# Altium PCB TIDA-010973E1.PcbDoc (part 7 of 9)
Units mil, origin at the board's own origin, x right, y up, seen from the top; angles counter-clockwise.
Board outline 5166 x 3669 mil, 8 copper layers (L01 - TOP, L02 - GND, L03 - SIG, L04 - GND, L05 - PWR, L06 - SIG, L07 - GND, L08 - BOTTOM), stack 61.7 mil thick; 677 components, 493 nets, 2522 pads, 1424 vias.
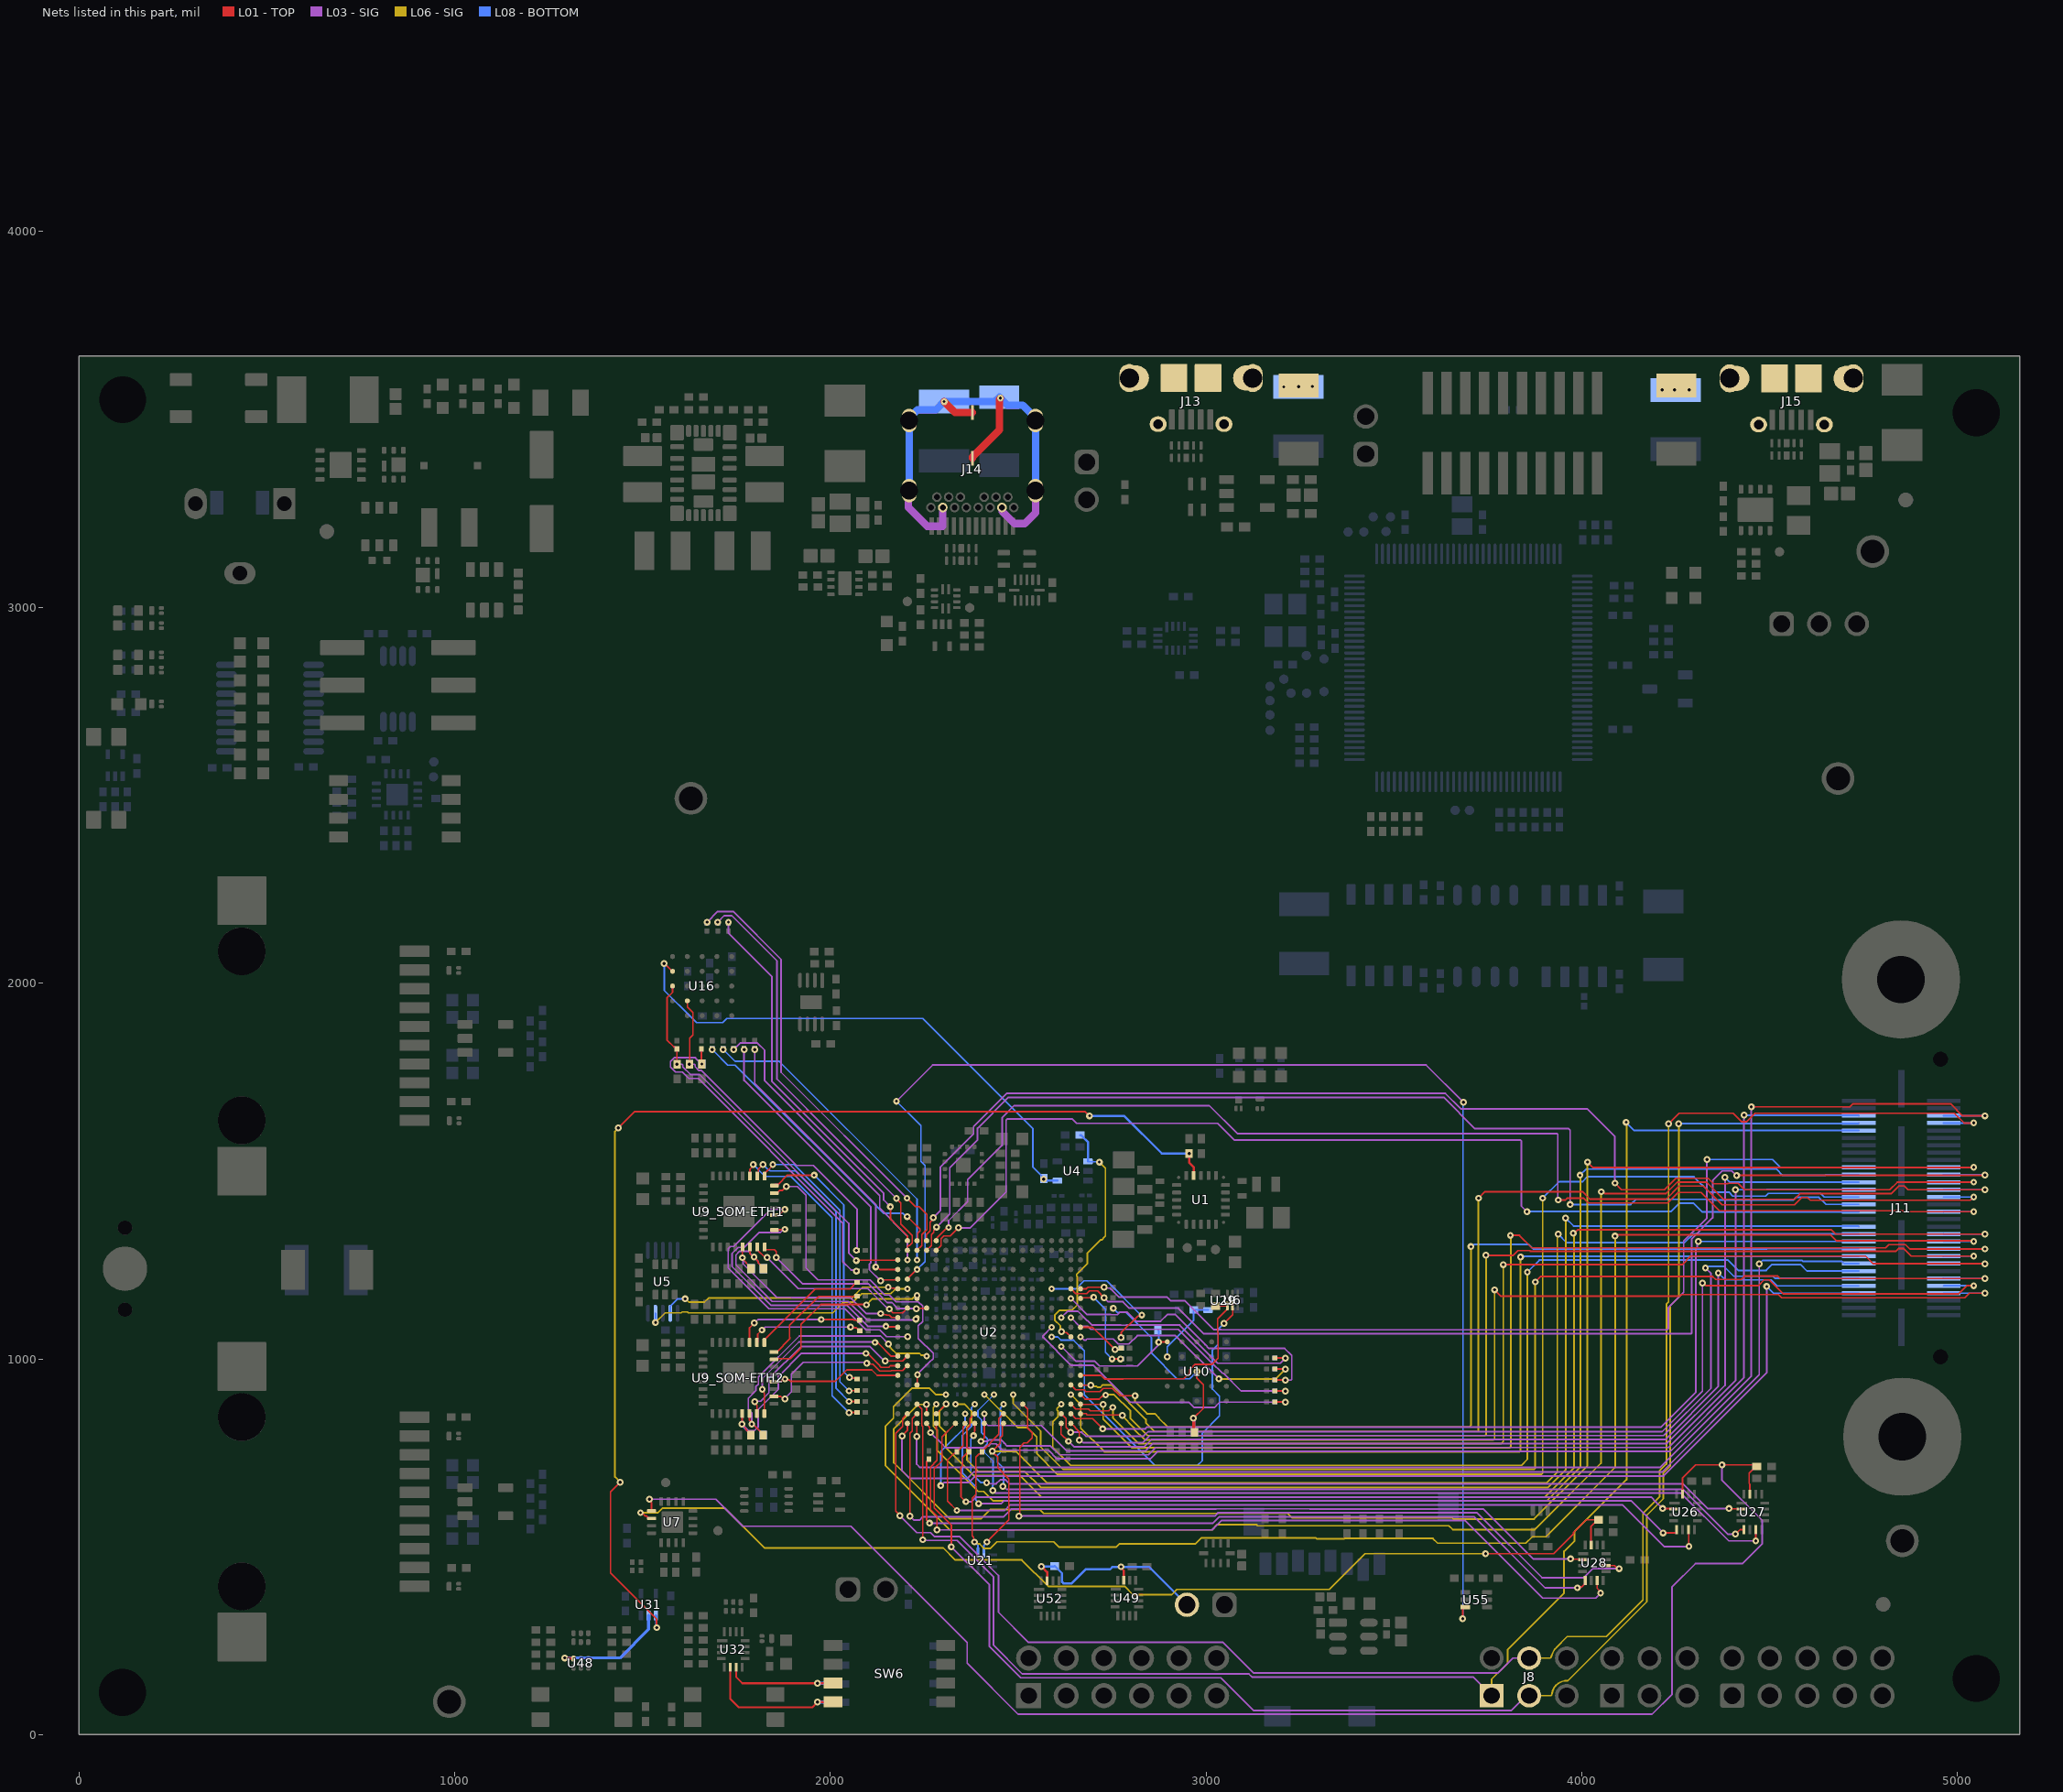
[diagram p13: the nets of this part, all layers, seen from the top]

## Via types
v1: diameter 18, hole 8, L01 - TOP to L08 - BOTTOM, tented both sides, 1389 vias
v2: diameter 19.68, hole 7.87, L01 - TOP to L08 - BOTTOM, 24 vias
v3: diameter 19.68, hole 7.87, L01 - TOP to L08 - BOTTOM, tented both sides, 11 vias

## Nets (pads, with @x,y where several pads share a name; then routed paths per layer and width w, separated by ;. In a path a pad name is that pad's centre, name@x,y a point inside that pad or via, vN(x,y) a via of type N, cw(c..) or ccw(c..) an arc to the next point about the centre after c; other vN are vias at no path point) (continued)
OSPI0_D0: R37.1 R45.2 U2.M3 | length 722.6
  L01 - TOP w4.5: R45.2@3183.13,1002.64 3183.45,1002.32 3210.68,1002.32 v1(3211,1002)
  L03 - SIG w4.5: v1(2614.68,1110) 2631.83,1127.15 2658.6,1127.15 2683.75,1102 2684.74,1102 2696.74,1090 2729.83,1090 2772.75,1090 2772.9,1089.85 2787.1,1089.85 2787.25,1090 2930,1090 3031.19,988.81 3197.81,988.81 v1(3211,1002)
  L08 - BOTTOM w4.5: R37.1@3183.13,1002.64 3183.45,1002.32 3210.68,1002.32 v1(3211,1002)
OSPI0_D1: R38.1 R46.2 U2.M2 | length 708.1
  L01 - TOP w4.5: R46.2@3183.13,914.89 3183.45,914.57 3210.68,914.57 v1(3211,914.25)
  L03 - SIG w4.5: v1(2640.27,1110) 2663.77,1086.5 2685.53,1086.5 2693.03,1079 2729.83,1079 2926.15,1079 3013.65,991.5 3013.9,991.5 3043.7,961.7 3046.3,961.7 3093,915 3195.85,915 3210.25,915 v1(3211,914.25)
  L08 - BOTTOM w4.5: R38.1@3183.13,914.89 3183.45,914.57 3210.68,914.57 v1(3211,914.25)
OSPI0_D2: R39.1 R47.2 U2.P1 | length 267.2
  L01 - TOP w4.3: U2.P1@2665.86,1161.18 2667.67,1162.99 2699.99,1162.99 v1(2701,1164) ; v1(2750,1000) v1(2772.6,1000) R47.2@2773.98,1000
  L08 - BOTTOM w4.3: v1(2701,1164) 2732.54,1132.46 2732.54,1017.46 v1(2750,1000) v1(2772.6,1000)
OSPI0_D3: R40.1 R48.2 U2.L1 | length 152.4
  L01 - TOP w4.3: U2.L1@2665.86,1084.41 2698.33,1084.41 2729.83,1052.91 v1(2757.62,1025.12) 2769.53,1025.12 2769.8,1024.85 R48.2@2773.95,1029
  L08 - BOTTOM w4.3: v1(2757.62,1025.12) 2770.07,1025.12 R40.1@2773.95,1029
OSPI0_D4: R41.1 R49.2 U2.R4 | length 373.9
  L01 - TOP w4.3: v1(2773.98,1057) 2773.98,1069.95 2818.4,1114.38 2826.38,1114.38 v1(2829,1117)
  L08 - BOTTOM w4.3: v1(2589.09,1186.77) 2653.59,1186.77 2674.87,1208.05 2729.83,1208.05 2735.66,1208.05 2826.71,1117 v1(2829,1117)
OSPI0_D5: R42.1 R50.2 U2.K1 | length 679.1
  L01 - TOP w4.5: R50.2@3183.13,973.39 3183.45,973.07 3210.68,973.07 v1(3211,972.75)
  L03 - SIG w4.5: v1(2665.86,1058.82) 2666.93,1058.82 2675.24,1050.5 2680.25,1050.5 2683.01,1053.26 2729.83,1053.26 2753.31,1053.26 2766.72,1039.85 2794.83,1039.85 2817.23,1062.25 2918.75,1062.25 v1@3033.89,947.11
  L06 - SIG w4.5: v1(3034,947) 3185.25,947 v1(3211,972.75)
  L08 - BOTTOM w4.5: R42.1@3183.13,973.39 3183.45,973.07 3210.68,973.07 v1(3211,972.75)
OSPI0_D6: R43.1 R53.2 U2.P2 | length 809.5
  L01 - TOP w4.5: R53.2@3183.13,944.14 3183.45,943.82 3210.68,943.82 v1(3211,943.5)
  L03 - SIG w4.5: v1(2640.27,1161.18) 2682.64,1118.81 2729.83,1118.81 2745.34,1118.81 2746.3,1117.85 2763.55,1117.85 2769.85,1124.15 2790.83,1124.15 2815.13,1099.85 2836.1,1099.85 2836.76,1100.5 2879.1,1100.5 2897.41,1118.81 2917.19,1118.81 2997.68,1038.32 3007.78,1028.18 3209.21,1028.18 3228.25,1009.14 3228.25,946.14 3225.61,943.5 v1(3211,943.5)
  L08 - BOTTOM w4.5: R43.1@3183.13,944.14 3183.45,943.82 3210.68,943.82 v1(3211,943.5)
OSPI0_D7: R44.1 R54.2 U2.L4 | length 820.8
  L01 - TOP w4.5: R54.2@3183.13,885.64 3183.45,885.32 3210.68,885.32 v1(3211,885)
  L03 - SIG w4.5: v1(2589.09,1084.41) 2566.03,1061.35 2566.03,1057.62 2640.18,983.48 2699.52,983.48 2729.83,953.17 2798,885 2803.75,885 2803.9,884.85 2954.41,884.85 2968.46,870.8 3022.03,870.8 3036.23,885 v1(3211,885)
  L08 - BOTTOM w4.5: R44.1@3183.13,885.64 3183.45,885.32 3210.68,885.32 v1(3211,885)
OSPI0_DQS: R33.1 R51.2 R182.1 U10.C3 | length 552.6
  L01 - TOP w4.5: v1(2966.35,842.19) 2992.81,868.65 2992.81,931.21 2975.56,948.46 v1(2975.56,966.69)
  L01 - TOP w8: v1(2966.35,842.19) 2967.74,840.8 2967.74,805.71 R33.1@2969.13,804.32
  L08 - BOTTOM w4.3: v1(2753.4,1135) 2753.55,1135 2764.4,1124.15 2787.1,1124.15 2854.94,1056.31 2854.94,1015.19 2922.78,947.35 2956.22,947.35 v1(2975.56,966.69)
  L08 - BOTTOM w8: v1(2966.35,842.19) 2967.74,840.8 2967.74,805.71 R51.2@2969.13,804.32
OSPI0_ECC_FAIL: R35.1 U2.J3 U10.A5 | length 367.5
  L01 - TOP w4.3: v1(2874,1045) 2874.22,1045.22 2896.6,1045.22 U10.A5@2896.82,1045.43
  L03 - SIG w4.5: v1(2614.68,1033.23) 2654.03,993.88 2703.83,993.88 2716.46,981.25 2729.83,981.25 2789,981.25 2789.9,982.15 2804.1,982.15 2805,981.25 2817.68,981.25 2871.42,1034.99 2871.42,1042.42 v1(2874,1045)
  L08 - BOTTOM w4.3: R35.1@2872,1076.32 2874,1074.32 v1(2874,1045)
OSPI0_RESET_OUT: U2.K4 U6.2 | length 1075.9
  L01 - TOP w3.5: v1(3048,1095) 3070.5,1117.5 U6.2@3070.5,1140.79
  L08 - BOTTOM w4.3: v1(2589.09,1058.82) 2605.07,1058.82 2613.61,1050.28 2647.33,1050.28 2675.95,1021.66 2675.95,904.94 2863.68,717.21 2977.47,717.21 2989.85,729.6 2989.85,802.45 3035.65,848.25 3035.65,901.22 3016.85,920.01 3016.85,1023.1 3032.08,1038.33 3032.08,1079.08 v1(3048,1095)
OSPI0_RSTN: R193.2 U10.A4 U29.4 | length 191.3
  L08 - BOTTOM w4.5: v1(2896.82,1006.06) 2896.82,1032.82 2967,1103 2967,1129.13 2968.28,1130.41 U29.4@3005.65,1130.41
OSPI1_CLK: R185.1 R189.1 R191.2 U16.B2 | length 896.9
  L01 - TOP w4.3: U16.B2@1619.63,1953 1619.63,1936.43 1634.47,1921.59 1634.47,1862.16 1625.78,1853.46 1625.78,1785.15 v1(1625,1784.37)
  L03 - SIG w4.5: v1(1625,1784.37) 1625.16,1784.21 1638.11,1784.21 1640.75,1781.57 1640.75,1777.54 1650.85,1767.44 1657.26,1767.44 1909.7,1515 1955.4,1515 2070.98,1399.42 v1@2070.98,1289
  other v1: 2069.6,1289
OSPI1_CSN0: R83.1 R188.1 U2.V20 U16.A3 | length 1080.7
  L01 - TOP w4.3: U16.A3@1580.26,1992.37 1580.26,1975.8 1565.42,1960.96 1565.42,1848.7 1584.2,1829.91 1587.85,1829.91 1592,1825.76 R83.1@1592,1824.98 v1(1592,1784.37) ; v1(2069,1262) 2069.77,1262.77 2178.87,1262.77 U2.V20@2179.64,1263.54
  L03 - SIG w4.5: v1(1592,1784.37) 1592.16,1784.21 1605.11,1784.21 1607.75,1781.57 1607.75,1777.23 1628.04,1756.94 1652.91,1756.94 2049,1360.85 2049,1282 v1(2069,1262)
OSPI1_D0: R66.1 R74.1 U2.V19 | length 812.9
  L03 - SIG w4.5: v1(1743,1823.62) 1760.23,1840.85 1806.15,1840.85 1825.5,1821.49 1825.5,1740.65 2131.5,1434.65 2131.5,1401.25 2205.23,1327.52 v1(2205.23,1263.54)
OSPI1_D1: R67.1 R75.1 U2.Y18 | length 785.9
  L01 - TOP w4.3: v1(2205,1379) 2217.11,1366.89 2238.72,1345.28 2238.72,1340.72 2232.66,1334.66 U2.Y18@2232.66,1320.49 ; U2.Y18@2230.82,1314.72 2232.63,1316.54 U2.Y18@2232.63,1320.47
  L08 - BOTTOM w4.3: v1(2205,1379) 2201.29,1379 2192.44,1387.85 2141.15,1387.85 1747,1782 1727.27,1782 1689.82,1819.45 1689.82,1820.04 R67.1@1686.26,1823.6 ; R67.1@1686.26,1823.6 v1(1685.67,1823.6) R67.1@1686.26,1823.6
OSPI1_D2: R68.1 R76.1 U2.W18 | length 1212.4
  L01 - TOP w3.5: v1(2204,1428) 2227.21,1404.79 2236.21,1404.79 2256.65,1384.35 2256.65,1366.89 2256.65,1344.79 2243.4,1331.54 2243.4,1301.71 U2.W18@2230.82,1289.13
  L03 - SIG w4.5: v1(1672,2162.4) 1700.6,2191 1741.24,2191 1869,2063.24 1869,1763 v1(2204,1428)
OSPI1_D3: R69.1 R77.1 U2.Y19 | length 1044.9
  L01 - TOP w4.3: v1(2160,1405) 2160,1372.75 2165.86,1366.89 2205.23,1327.52 U2.Y19@2205.23,1314.72
  L03 - SIG w4.5: v1(1729,2162.4) 1729,2133 1845,2017 1845,1738.15 2142,1441.15 2142,1423 v1(2160,1405)
OSPI1_D4: R70.1 R78.1 U2.W19 | length 1140.2
  L01 - TOP w3.5: v1(2176,1427) 2188,1415 2188,1366.89 2188,1358.61 2217.8,1328.8 2217.8,1309.52 2210.44,1302.15 2208.34,1302.15 2205.36,1299.17 2205.36,1289.27 U2.W19@2205.23,1289.13
  L03 - SIG w4.5: v1(1700.5,2162.4) 1717.75,2179.65 1737.74,2179.65 1858,2059.4 1858,1745 2013.46,1589.54 v1(2176,1427)
OSPI1_D5: R71.1 R79.1 U2.U20 | length 773.5
  L01 - TOP w4.3: v1(2121,1245) 2124.71,1245 2131.75,1237.95 U2.U20@2179.64,1237.95
  L03 - SIG w4.5: v1(1799,1823.6) 1799,1733 2121,1411 v1(2121,1245)
OSPI1_D6: R72.1 R80.1 U2.T20 | length 817.2
  L01 - TOP w4.3: v1(2134,1208) 2136.55,1210.55 2177.82,1210.55 U2.T20@2179.64,1212.36
  L03 - SIG w4.5: v1(1770.67,1823.6) 1770.67,1741.33 2107.89,1404.11 2107.89,1256.29 2103.75,1252.15 2103.75,1237.85 2133.6,1208 v1(2134,1208)
OSPI1_D7: R73.1 R81.1 U2.V18 | length 842.6
  L08 - BOTTOM w4.3: v1(1715,1823.6) 1715.59,1823.6 1746.89,1792.3 1863.95,1792.3 2230.82,1425.43 v1(2230.82,1263.54)
OSPI1_DQS: R82.1 R187.1 R190.2 R232.1 | length 930.7
  L01 - TOP w4.3: R187.1@1657.33,1785.35 R82.1@1657.33,1824.98
  L01 - TOP w5.3: R187.1@1657.33,1785.35 v1(1658,1784.69) ; v1(2069.6,1234) R232.1@2070.98,1234
  L03 - SIG w4.5: v1(1658,1784.69) 1641.07,1801.62 1584.86,1801.62 1574.75,1791.52 1574.75,1777.23 1588.27,1763.7 1606.43,1763.7 1623.69,1746.44 1648.56,1746.44 2033,1362 2033,1259.38 2055.8,1236.58 2067.02,1236.58 v1(2069.6,1234)
OSPI1_RESET_OUT: R9.1 U2.K2 U4.1 | length 686.2
  L01 - TOP w4.5: v1(2615,1073) 2617.58,1070.42 2628.67,1070.42 U2.K2@2640.27,1058.82
  L06 - SIG w4.5: v1(2615,1073) 2612.42,1075.58 2612.42,1088.01 2597.53,1102.9 2597.53,1117.1 2610.15,1129.72 2643.15,1129.72 2657.42,1143.99 2657.42,1219.47 2655.68,1221.2 2655.68,1224.93 2683.85,1253.1 2683.85,1281.59 2719.1,1316.85 2722.1,1316.85 2729.83,1324.58 2732.15,1326.9 2732.15,1329.9 2732.25,1330 2732.25,1507.75 v1(2716,1524)
  L08 - BOTTOM w4.5: U4.1@2685.35,1525.59 2686.15,1524.8 2715.2,1524.8 v1(2716,1524)
  L08 - BOTTOM w6: R9.1@2664.68,1596 2666.65,1596 2679.81,1582.84 2680.22,1582.84 2685.5,1577.57 2685.5,1525.73 U4.1@2685.35,1525.59
OSPI1_RSTN: R10.2 U4.4 U16.A4 | length 1428.8
  L01 - TOP w4.3: v1@1559,2052 U16.A4@1579.26,2031.74
  L01 - TOP w6: v1(1558,2052) v1@1559,2052 ; U16.A4@1579.26,2031.74 U16.A4@1580.26,2031.74
  L08 - BOTTOM w4.3: v1(1558,2052) 1558,1981.14 1633.14,1906 1644.13,1895.01 1713.87,1895.01 1724.86,1906 2246.54,1906 2538.89,1613.65 2538.89,1511.39 2568,1482.28 R10.2@2568,1480.31 v1(2568,1478.35)
  L08 - BOTTOM w6: R10.2@2568.98,1479.33 2573.91,1474.41 U4.4@2604.65,1474.41
OSPI_BUF_EN: R7.1 U2.F1 U6.1 | length 579.7
  L01 - TOP w4.3: U2.F1@2665.86,956.46 2720.11,956.46 2729.72,946.85 2779.6,946.85 2779.9,947.15 2940.9,947.15 2956.69,962.94 2956.69,972.08 2970.09,985.47 3015.33,985.47 3032.08,1002.22 3032.08,1071.78 3030.85,1073.01 3030.85,1106.46 3056.72,1132.32 U6.1@3056.72,1140.79 3025.58,1140.79 R7.1@3025.37,1141
PMIC_NRST: R202.2 U1.17 U31.1 | length 3081.2
  L01 - TOP w4.5: v1(1436,1615) 1479,1658 2678.73,1658 2689.73,1647 v1(2690,1647) ; v1(1441,672) 1415,646 1415,431 1538,308 v1(1538,285)
  L01 - TOP w6: v1(2955,1546.97) 2955,1522.75 2967.08,1510.67 U1.17@2967.08,1488.38
  L06 - SIG w4.5: v1(1436,1615) 1436,1614.83 1426.81,1605.64 1426.81,686.19 v1(1441,672)
  L08 - BOTTOM w6: U31.1@1535.84,317.48 1536.92,316.4 1536.92,286.08 v1(1538,285) ; v1(2690,1647) 2781.98,1647 2882.02,1546.97 v1(2955,1546.97)
PORZ_PB: U31.2 U48.6 | length 315.7
  L01 - TOP w8: v1(1293.24,204.46) 1294.33,203.37 1315.46,203.37 U48.6@1316.55,202.28
  L08 - BOTTOM w8: v1(1293.24,204.46) 1440.33,204.46 1516.16,280.29 U31.2@1516.16,317.48
PR0_IEP0_EDC_LATCH_IN0: J8.3 J11.53 U2.A14 | length 4410
  L01 - TOP w4.3: v1(2322,500) 2322,558.57 2276.85,603.72 2276.85,708.27 2297,728.42 2297,792.32 U2.A14@2333.18,828.5
  L03 - SIG w4.5: v1(2322,500) 2423.5,398.5 2423.5,234.5 2506.5,151.5 3039.49,151.5 3126.74,64.25 3812.16,64.25 3851.91,104 J8.3@3860,104
  L06 - SIG w4.5: J8.3@3860,104 3915.98,104 3917.62,104 3920.25,106.64 3920.6,109.25 cw(c3960,104) 3960.83,143.74 3962.74,143.74 4173,354 4173,584.39 4217.25,628.64 4217.25,697.49 4235.5,715.74 4235.5,1141.9 4258,1164.4 v1(4258,1626)
  L08 - BOTTOM w4.5: v1(4258,1626) 4258.93,1626.93 4736.28,1626.93 J11.53@4737.2,1627.86
PR0_IEP0_EDC_LATCH_IN1: J8.4 J11.54 U2.B19 | length 4811.4
  L01 - TOP w3.5: v1(2185,583) 2185,583.63 2174,594.63 2174,802.25 2192.29,820.54 2192.29,841.15 U2.B19@2205.23,854.09
  L01 - TOP w4.5: v1(4231,1626) 4259,1654 4402.6,1654 4424.85,1631.75 4439.15,1631.75 4461.15,1653.75 4991.65,1653.75 5017.33,1628.07 v1(5043,1628.07)
  L03 - SIG w4.5: v1(2185,583) 2230.15,537.85 2266.75,537.85 2276.85,527.75 2343.85,527.75 2447.75,423.85 2447.75,325.85 2527.89,245.71 3045.28,245.71 3126.74,164.25 3776.46,164.25 3816.21,204 J8.4@3860,204
  L06 - SIG w4.5: J8.4@3860,204 3915.98,204 3918.62,206.64 3922.7,217.72 cw(c3960,204) 3931.9,232.1 3960.97,261.18 4065.33,261.18 4162.5,358.35 4162.5,588.74 4206.75,632.99 4206.75,701.84 4225,720.09 4225,1146.24 4231,1152.24 v1(4231,1626)
  L08 - BOTTOM w4.5: J11.54@4962.8,1627.86 4962.9,1627.96 5042.89,1627.96 v1(5043,1628.07)
PR0_IEP0_EDC_SYNC_OUT0: J8.1 J11.51 U2.C18 | length 4463.6
  L01 - TOP w3.5: U2.C18@2230.82,879.69 2243.83,866.67 2243.83,823.29 2246.65,820.48 2246.65,785.2 2246.35,784.9 2246.35,776.34 2246.35,519.35 v1(2246,519)
  L03 - SIG w4.5: v1(2246,519) 2247.75,517.25 2337.75,517.25 2434,421 2434,239.01 2511.01,162 3114.14,162 3122.39,153.75 3710.25,153.75 J8.1@3760,104
  L06 - SIG w4.5: J8.1@3760,104 3760,147.79 3803,190.79 3803,227 3952.75,376.75 3952.75,488.35 3980.75,516.35 3980.75,541.15 3990.85,551.25 3991.25,551.25 4119,679 4119,1629 v1(4118,1630)
  L08 - BOTTOM w4.5: v1(4118,1630) 4139.83,1608.17 J11.51@4737.2,1608.17
PR0_IEP0_EDC_SYNC_OUT1: U2.T19 U55.3 | length 3524.8
  L01 - TOP w3.5: U2.T19@2205.23,1212.36 2230.87,1238 v1(2231,1238)
  L01 - TOP w4.5: v1(3683,309) 3683,335.97 3686.66,339.63 U55.3@3689.76,339.63
  L03 - SIG w4.5: v1(2176,1686) 2272.44,1782.44 3585.56,1782.44 v1(3685,1683)
  L08 - BOTTOM w4.3: v1(2176,1686) 2241.22,1620.78 2241.22,1525.88 2252,1515.1 2252,1259 v1(2231,1238)
  L08 - BOTTOM w4.5: v1(3683,309) 3683.75,309.75 3683.75,1681.75 v1(3685,1683)
PR0_MII0_RXD0: U2.N17 U9_SOM-ETH1.16 | length 512.1
  L01 - TOP w4.3: U9_SOM-ETH1.16@1825.54,1297.99 1825.54,1293.87 1828.31,1291.1 1850.9,1291.1 1856,1286 v1(1856,1270) ; v1(2229,1134) 2229.8,1134.8 2255.61,1134.8 U2.N17@2256.41,1135.59
  L03 - SIG w4.3: v1(1856,1270) 1925.65,1200.35 2100.9,1200.35 2127.47,1173.78 2127.47,1173.64 2151.06,1150.05 2164.06,1150.05 2174.05,1140.06 2174.05,1138.77 2178.82,1134 v1(2229,1134)
PR0_MII0_RXD1: U2.N19 U9_SOM-ETH1.15 | length 481.7
  L01 - TOP w3.9: v1(2157,1133) 2167.2,1122.8 2185.19,1122.8
  L01 - TOP w4.3: U9_SOM-ETH1.15@1805.86,1297.99 1808.89,1294.96 1808.89,1287.54 1823.81,1272.62 1829.38,1272.62 v1(1832,1270) ; 2185.19,1122.8 2192.43,1122.8 U2.N19@2205.23,1135.59
  L03 - SIG w3.9: v1(1832,1270) 1915,1187 2099.97,1187 2117.37,1169.6 2117.37,1169.46 2126.88,1159.95 2127.02,1159.95 2127.47,1159.5 2146.92,1140.05 2147.67,1140.05 2154.72,1133 v1(2157,1133)
PR0_MII0_RXD2: R32_SOM-ETH1.2 R204_SOM-ETH1.1 U2.M18 U9_SOM-ETH1.14 | length 745.9
  L01 - TOP w4.3: U9_SOM-ETH1.14@1786.17,1297.99 1786.2,1279.73 1794.93,1271 v1(1797,1271) 1807.96,1260.04 1807.96,1256.47 1822.13,1242.29 R32_SOM-ETH1.2@1822.13,1240.32 ; v1(2228,1106) 2230.82,1108.82 U2.M18@2230.82,1110
  L03 - SIG w4.3: v1(1797,1271) 1781.21,1286.79 1759.03,1286.79 1748.98,1276.74 1748.98,1250.04 1845.62,1153.4 2047.78,1153.4 2097.23,1103.95 2126.94,1103.95 2127.47,1103.95 2141.06,1103.95 2141.16,1104.05 2155.06,1104.05 2155.16,1103.95 2225.95,1103.95 v1(2228,1106)
  L08 - BOTTOM w4.3: v1(1797,1271) 1807.96,1260.04 1807.96,1256.47 1822.13,1242.29 R204_SOM-ETH1.1@1822.13,1240.32
PR0_MII0_RXD3: R31_SOM-ETH1.2 R205_SOM-ETH1.1 U2.M20 U9_SOM-ETH1.13 | length 594.5
  L01 - TOP w3.5: v1(2134,1121) 2136.77,1118.23 2148.23,1118.23 2150.1,1116.35 2156.94,1116.35 2163.29,1110 U2.M20@2179.64,1110
  L01 - TOP w4.3: U9_SOM-ETH1.13@1766.49,1297.99 1766.31,1297.82 1766.31,1269.82 v1(1766.13,1269.64) 1766.13,1267.15 1776.41,1256.87 1776.41,1255.02 1789.13,1242.29 R31_SOM-ETH1.2@1789.13,1240.32
  L03 - SIG w4.3: v1(1766.13,1269.64) 1767.92,1267.86 1767.92,1253.09 1857,1164 1897.92,1164 1898.22,1163.7 2052.05,1163.7 2094.75,1121 2127.47,1121 v1(2134,1121)
  L08 - BOTTOM w4.3: v1(1766.13,1269.64) 1769.08,1266.69 1769.08,1262.35 1789.13,1242.29 R205_SOM-ETH1.1@1789.13,1240.32
PR0_MII0_RXDV: U2.L20 U9_SOM-ETH1.18 | length 738.4
  L01 - TOP w4.3: U9_SOM-ETH1.18@1851.13,1343.27 1852,1344.13 1878.13,1344.13 v1(1879,1345) ; v1(2148,1087) 2149.3,1085.7 2178.34,1085.7 U2.L20@2179.64,1084.41
  L03 - SIG w4.3: v1(1879,1345) 1875.29,1345 1866.59,1336.3 1810.3,1336.3 1771.09,1297.09 1754.76,1297.09 1738.68,1281.01 1738.68,1245.77 1841.36,1143.1 2043.51,1143.1 2099.61,1087 2127.47,1087 v1(2148,1087)
PR0_MII0_RXER: U2.K19 U9_SOM-ETH1.20 | length 832.3
  L01 - TOP w4.3: U9_SOM-ETH1.20@1851.13,1382.64 1852.93,1384.44 1865.44,1384.44 v1(1879,1398)
  L03 - SIG w3.5: v1(1879,1398) 1841.68,1398 1742.76,1299.09 1734.09,1299.09 1728.78,1293.78 1728.78,1241.67 1837.25,1133.2 2039.41,1133.2 2095.51,1077.1 2131.76,1077.1 2149.42,1059.44 v1(2205.85,1059.44)
PR0_MII0_TXD0: R234.2 U9_SOM-ETH1.24 | length 715.9
  L01 - TOP w4.3: U9_SOM-ETH1.24@1851.13,1461.38 1853.91,1464.15 1860.79,1464.15 1885.65,1489 v1(1957,1489) ; v1(2051,951) 2053,949 2068.98,949 R234.2@2070.98,947
  L08 - BOTTOM w4.3: v1(1957,1489) 2036,1410 2036,966 v1(2051,951)
PR0_MII0_TXD1: R235.2 U9_SOM-ETH1.25 | length 781
  L01 - TOP w4.3: U9_SOM-ETH1.25@1825.54,1486.97 1825.54,1493.86 1847.13,1515.45 v1(1847.13,1517.64) ; v1(2050,915) 2050.5,915.5 2070.48,915.5 R235.2@2070.98,916
  L08 - BOTTOM w4.3: v1(1847.13,1517.64) 1904.11,1517.64 2025.7,1396.05 2025.7,939.3 v1(2050,915)
PR0_MII0_TXD2: R236.2 U9_SOM-ETH1.26 | length 823.6
  L01 - TOP w4.3: U9_SOM-ETH1.26@1805.86,1486.97 1808.63,1489.74 1808.63,1505.28 v1(1820.99,1517.64) ; v1(2050,887) R236.2@2070.98,887
  L08 - BOTTOM w4.3: v1(1820.99,1517.64) 1836.63,1502 1838.52,1502 1840.03,1500.49 1906.69,1500.49 2015.4,1391.78 2015.4,921.6 v1(2050,887)
PR0_MII0_TXD3: R237.2 U9_SOM-ETH1.27 | length 862.3
  L01 - TOP w4.3: U9_SOM-ETH1.27@1786.17,1486.97 1786.17,1505.23 1794.85,1513.9 v1(1794.85,1517.64) ; v1(2050,857) 2050.5,857.5 2070.48,857.5 R237.2@2070.98,858
  L08 - BOTTOM w4.3: v1(1794.85,1517.64) 1826.45,1486.03 1895.22,1486.03 2005.1,1376.15 2005.1,901.9 v1(2050,857)
PR0_MII0_TXEN: U2.E18 U9_SOM-ETH1.23 | length 895.6
  L01 - TOP w3.5: U2.E18@2230.82,930.87 2231.41,931.46 2231.41,957.41 v1(2232,958)
  L01 - TOP w4.3: U9_SOM-ETH1.23@1851.13,1441.69 1853.91,1444.46 1860.79,1444.46 1864.64,1448.31 1871.84,1448.31 1882.54,1459 v1(1883,1459)
  L03 - SIG w3.5: v1(1883,1459) 1911.69,1459 1935.04,1435.65 1935.04,1242.27 1967.06,1210.25 2105.77,1210.25 2145.35,1170.67 2157.3,1170.67 2175.62,1152.35 2234.2,1152.35 2245.65,1140.9 2245.65,1100.1 2234.2,1088.65 2234.2,1054.65 2235.22,1053.62 2273.68,1015.16 2273.68,1001.37 2263.77,991.45 2232,959.68 v1(2232,958)
PR0_MII1_RXD0: U2.H20 U9_SOM-ETH2.16 | length 511.8
  L01 - TOP w4.3: v1(1819,919) 1819,915.29 1824.54,909.75 U9_SOM-ETH2.16@1824.54,854.99 ; v1(2119,1044) 2121.36,1041.64 2127.47,1041.64 2161.29,1007.82 2179.46,1007.82 U2.H20@2179.64,1007.64
  L03 - SIG w4.3: v1(1819,919) 1819,947.87 1916.44,1045.31 2117.69,1045.31 v1(2119,1044)
PR0_MII1_RXD1: U2.H19 U9_SOM-ETH2.15 | length 543.8
  L01 - TOP w3.5: v1(2146,995) 2192.59,995 U2.H19@2205.23,1007.64
  L01 - TOP w4.3: v1(1799,886) 1799,882.29 1804.93,876.36 1804.93,855.06 U9_SOM-ETH2.15@1804.86,854.99
  L03 - SIG w4.3: v1(1799,886) 1800.45,887.45 1814.45,887.45 1837,910 1837,948 1922,1033 2105.75,1033 2143.75,995 v1(2146,995)
PR0_MII1_RXD2: R32_SOM-ETH2.2 R204_SOM-ETH2.1 U2.H17 U9_SOM-ETH2.14 | length 775.9
  L01 - TOP w4.3: U9_SOM-ETH2.14@1785.17,854.99 1785.2,836.73 1791.13,830.8 v1(1791.13,826.64) 1793.81,826.64 1807.41,813.04 ; 1807.41,813.02 1821.13,799.29 R32_SOM-ETH2.2@1821.13,797.32
  L03 - SIG w4.3: v1(1791.13,826.64) 1791.13,857.08 1781.85,866.37 1781.85,895.37 1801.85,915.37 1801.85,926.1 1808.7,932.95 1808.7,952.14 1917.71,1061.15 2133.85,1061.15 v1(2155,1040)
  L06 - SIG w4.3: v1(2155,1040) 2155,1036.29 2159.13,1032.17 2159.13,1030.88 2163.21,1026.79 2174.95,1015.05 2237.06,1015.05 2241.85,1010.26 2253.79,1010.26 v1(2256.41,1007.64)
  L08 - BOTTOM w4.3: v1(1791.13,826.64) 1793.81,826.64 1807.41,813.04 ; 1807.41,813.02 1821.13,799.29 R204_SOM-ETH2.1@1821.13,797.32
PR0_MII1_RXD3: R31_SOM-ETH2.2 R205_SOM-ETH2.1 U2.G20 U9_SOM-ETH2.13 | length 677.1
  L01 - TOP w4.3: U9_SOM-ETH2.13@1765.49,854.99 1765.31,854.82 1765.31,826.82 v1(1765.13,826.64) 1765.13,824.15 1775.41,813.87 1775.41,812.02 1788.13,799.29 R31_SOM-ETH2.2@1788.13,797.32 ; v1(2095,1015) 2098.55,1015 2127.47,986.07 2135.6,977.95 2155.96,977.95 2160.05,982.05 U2.G20@2179.64,982.05
  L03 - SIG w4.3: v1(1765.13,826.64) 1782.28,809.49 1798.24,809.49 1808.28,819.53 1808.28,866.11 1861.98,919.81 1861.98,953.74 1923.24,1015 v1(2095,1015)
  L08 - BOTTOM w4.3: v1(1765.13,826.64) 1768.08,823.69 1768.08,819.35 1788.13,799.29 R205_SOM-ETH2.1@1788.13,797.32
PR0_MII1_RXDV: U2.G19 U9_SOM-ETH2.18 | length 442
  L01 - TOP w3.5: v1(2097,989) 2099.45,986.55 2113,986.55 2131.4,968.15 2161.71,968.15 2162.6,969.03 2192.21,969.03 U2.G19@2205.23,982.05
  L01 - TOP w4.3: U9_SOM-ETH2.18@1850.13,900.27 1850.19,900.21 1868.39,900.21 1874.97,893.64 v1(1879.13,893.64)
  L03 - SIG w4.3: v1(1879.13,893.64) 1879.13,895.38 1896.28,912.53 1896.28,959.58 1927.7,991 2095,991 v1(2097,989)
PR0_MII1_RXER: U2.F20 U9_SOM-ETH2.20 | length 353.5
  L01 - TOP w4.3: U9_SOM-ETH2.20@1850.13,939.64 1850.56,940.06 1868.39,940.06 1874.97,946.64 v1(1879.13,946.64) 1881.76,944.02 1890.89,944.02 1894.26,940.65 2013.65,940.65 2044,971 2110.25,971 2124.8,956.46 U2.F20@2179.64,956.46
PR0_MII1_TXD0: R208.2 U9_SOM-ETH2.24 | length 304.5
  L01 - TOP w3.5: 1892,1058 1892,1090 1969,1167 R208.2@2071.57,1167
  L01 - TOP w4.3: U9_SOM-ETH2.24@1850.13,1018.38 1857.02,1018.38 1892,1053.35 1892,1058
PR0_MII1_TXD1: R209.2 U9_SOM-ETH2.25 | length 315.4
  L01 - TOP w3.5: 1835.34,1061.65 1960.32,1186.64 2052.24,1186.64 R209.2@2069.6,1204
  L01 - TOP w4.3: U9_SOM-ETH2.25@1824.54,1043.97 1824.54,1050.86 1835.34,1061.65
PR0_MII1_TXD2: R210.2 U9_SOM-ETH2.26 | length 305.9
  L01 - TOP w4.3: U9_SOM-ETH2.26@1804.86,1043.97 1806.94,1046.05 1806.94,1065.94 v1(1818,1077) ; v1(2054,1085) 2055.88,1083.12 2069.45,1083.12 2073.43,1079.15 2074.02,1079.15 2077.57,1075.59 R210.2@2077.57,1075
  L03 - SIG w4.3: v1(1818,1077) 1819.37,1077 1827.37,1085 v1(2054,1085)
PR0_MII1_TXD3: R211.2 U9_SOM-ETH2.27 | length 341.9
  L01 - TOP w4.3: U9_SOM-ETH2.27@1785.17,1043.97 1785.17,1083.17 v1(1798,1096) ; v1(1976,1105) 2061.71,1105 2063.46,1103.25 2077.73,1103.25 R211.2@2077.98,1103
  L03 - SIG w4.3: v1(1798,1096) 1798.29,1096 1807.29,1105 v1(1976,1105)
PR0_MII1_TXEN: U2.P18 U9_SOM-ETH2.23 | length 501.8
  L01 - TOP w4.3: U9_SOM-ETH2.23@1850.13,998.69 1852.91,1001.46 1853.43,1000.94 1893.94,1000.94 1922,1029 1922,1092 1975,1145 2095,1145 v1(2096,1144) ; U2.P18@2230.91,1156.91 2230.91,1168.91 v1(2231,1169) v1@2231.08,1169.08
  L06 - SIG w4.3: v1(2096,1144) 2112.15,1160.15 2218.44,1160.15 2227.29,1169 v1(2231,1169)
PR0_MII_MDC: U2.R20 U5.7 | length 653.5
  L01 - TOP w3.5: v1(2154,1191) 2156.26,1188.74 2177.67,1188.74 U2.R20@2179.64,1186.77
  L06 - SIG w4.5: v1(1614,1160) 1614.68,1160 1623.39,1151.3 1665.3,1151.3 1676,1162 2057,1162 2085.85,1190.85 2127.47,1190.85 v1@2153.85,1190.85
  L08 - BOTTOM w4.3: U5.7@1574,1121.68 1574,1139.39 1594.61,1160 v1(1614,1160)
PR0_MII_MDIO: U2.R19 U5.9 | length 734.5
  L06 - SIG w4.5: v1(1535,1097) 1560.75,1122.75 1603.35,1122.75 1605.85,1125.25 1620.15,1125.25 1622.65,1122.75 2006.75,1122.75 2035.5,1151.5 2061.35,1151.5 2083.7,1173.85 2161.1,1173.85 2171.15,1183.9 2171.15,1184.14 2173.79,1186.77 v1(2205.23,1186.77)
  L08 - BOTTOM w4.5: U5.9@1534.63,1121.68 1535,1121.31 v1(1535,1097)
PR1_MDIO0_MDC: J11.56 U2.A18 | length 3899.6
  L01 - TOP w4.5: v1(2230,794) 2230.41,794.41 2230.41,828.09 U2.A18@2230.82,828.5 ; v1(4451,1671) 4713.7,1671 4721.95,1679.25 4981,1679.25 5013.25,1647 v1(5073,1647)
  L03 - SIG w4.5: v1(2230,794) 2230,720 2238.76,711.24 4207.24,711.24 4451,955 v1(4451,1671)
  L08 - BOTTOM w4.5: J11.56@4962.8,1647.54 4963.07,1647.27 5072.73,1647.27 v1(5073,1647)
PR1_MDIO0_MDIO: J11.55 U2.A17 | length 3324.9
  L01 - TOP w4.3: U2.A17@2256.41,828.5 2256.41,825.94 2264.38,817.97 2264.38,806.62 v1(2267,804)
  L03 - SIG w4.5: v1(2267,804) 2294.66,776.34 2307.15,763.85 2408.1,763.85 2412.88,768.62 2421.4,768.62 2427.06,774.29 2441.35,774.29 2458.6,757.04 2580.67,757.04 2603.21,734.5 2851.41,734.5 2870.91,754 4235.15,754 4431,949.85 4431,1648 v1(4432,1649)
  L08 - BOTTOM w4.5: v1(4432,1649) 4432.73,1648.27 4736.48,1648.27 J11.55@4737.2,1647.54
PR1_PRU0_GPIO0: R123.2 U2.B12 U26.2 | length 2166.7
  L01 - TOP w3.5: 2363.79,797.21 2363.79,815.73 2371.35,823.29 2371.35,841.08 U2.B12@2384.36,854.09
  L01 - TOP w4.3: v1(2361,620) 2347.85,633.15 2347.85,711.82 2352.27,716.23 2352.27,738.15 2365.2,751.09 2368.85,751.09 2373,755.24 2373,756.81 2368.85,760.96 2368.06,760.96 2363.79,765.24 2363.79,797.21
  L01 - TOP w4.5: v1(4215,602) 4215.56,601.44 4243.94,601.44 U26.2@4244.5,600.87
  L03 - SIG w4.5: v1(2361,620) 2375.6,620 2388.15,632.55 4184.45,632.55 4197,620 v1(4215,602)
PR1_PRU0_GPIO1: U2.C12 U26.5 | length 2200.2
  L01 - TOP w4.3: v1(4216,537) 4250.59,537 4252.38,538.79 U26.5@4252.38,545.76
  L03 - SIG w4.5: v1(2395,615) 2455,615 2462.15,622.15 4132.26,622.15 4216,538.41 v1(4216,537)
  L08 - BOTTOM w4.3: v1(2384.36,879.69) 2384.36,878.76 2375.92,870.32 2375.92,820.96 2351.81,796.84 2351.81,776.34 2351.81,695.89 2387.63,660.07 2387.63,624.37 2395,617 v1(2395,615)
PR1_PRU0_GPIO2: J11.7 U2.B13 | length 3022.8
  L03 - SIG w4.5: v1(2294,663) 2294.89,663 2303.39,671.5 2368.64,671.5 2385.89,688.75 4217.75,688.75 4492,963 v1(4492,1193)
  L08 - BOTTOM w4.5: v1(2294,663) 2294,753.6 2316.74,776.34 2358.77,818.37 v1(2358.77,854.09) ; v1(4492,1193) 4509.9,1175.1 J11.7@4737.2,1175.1
PR1_PRU0_GPIO3: J11.8 U2.B1 | length 2963.7
  L01 - TOP w3.5: U2.B1@2665.86,854.09 2681.6,854.09 2684.1,851.6 2729.83,851.6 2775.4,851.6 v1(2777,850)
  L01 - TOP w4.3: v1(3768,1184) 3768.29,1184 3785.29,1167 4260.75,1167 4264.9,1171.15 4523.54,1171.15 4531.99,1162.7 5018.88,1162.7 5031.18,1175 5050.62,1175 v1(5073,1175)
  L06 - SIG w4.5: v1(2777,850) 2777,848.5 2808.29,817.21 2808.29,813.71 2837,785 3765.36,785 3768,787.64 v1(3768,1184)
  L08 - BOTTOM w4.3: J11.8@4962.8,1175.1 J11.8@4962.8,1175.1 5072.95,1175.05 v1(5073,1175)
PR1_PRU0_GPIO4: J11.9 U2.A3 | length 2548.1
  L01 - TOP w3.5: U2.A3@2614.68,828.5 2614.68,800.32 v1(2634,781)
  L03 - SIG w4.5: v1(2634,781) 2649,766 2835.15,766 2854.65,785.5 4222.1,785.5 4363,926.4 v1(4363,1229)
  L08 - BOTTOM w4.3: v1(4363,1229) 4381.85,1210.15 4503.85,1210.15 4519.21,1194.79 J11.9@4737.2,1194.79
PR1_PRU0_GPIO5: J11.10 U2.B3 | length 2918.4
  L01 - TOP w3.5: U2.B3@2614.68,854.09 2627.25,841.52 2627.25,817.75 v1(2640,805)
  L01 - TOP w4.3: v1(4321,1202) 4323.37,1202 4330.37,1195 4469.75,1195 4484.9,1210.15 4499.1,1210.15 4536.25,1173 5002.22,1173 5024.22,1195 v1(5043,1195)
  L03 - SIG w4.5: v1(2640,805) 2669.4,805 2680,794.4 2833.85,794.4 2845.95,806.5 4213.4,806.5 4321,914.1 v1(4321,1202)
  L08 - BOTTOM w4.3: J11.10@4962.8,1194.79 4962.9,1194.89 5042.89,1194.89 v1(5043,1195)
PR1_PRU0_GPIO6: J11.11 U2.A2 | length 2546.8
  L01 - TOP w3.5: U2.A2@2640.27,828.5 2663,805.77 v1(2663,784)
  L03 - SIG w4.5: v1(2663,784) 2665.64,784 2672.39,777.25 2729.73,777.25 2729.83,777.35 2831.65,777.35 2850.3,796 4217.75,796 4344,922.25 4344,1227 v1(4329,1242)
  L08 - BOTTOM w4.3: v1(4329,1242) 4332.71,1242 4336.86,1246.15 4378.85,1246.15 4404.55,1220.45 4508.12,1220.45 4514.09,1214.47 J11.11@4737.2,1214.47
PR1_PRU0_GPIO7: J11.12 U2.D8 | length 3329.9
  L01 - TOP w4.5: v1(3876,1205) 3890.25,1219.25 4348.35,1219.25 4355.85,1211.75 4424.13,1211.75 4432.93,1220.55 4521.42,1220.55 4527.97,1214 v1(5073,1214)
  L06 - SIG w4.5: v1(2486.72,905.28) 2486.72,881.41 2559.81,808.32 2559.81,766.08 2619.28,706.61 3873.36,706.61 3876,709.25 v1(3876,1205)
  L08 - BOTTOM w4.5: J11.12@4962.8,1214.47 4963.03,1214.24 5072.76,1214.24 v1(5073,1214)
PR1_PRU0_GPIO8: J11.13 U2.C3 | length 2835.1
  L06 - SIG w4.5: v1(2614.68,879.69) 2603.08,868.09 2603.08,864.36 2606.24,861.2 2606.24,846.99 2592,832.75 2592,764.5 2639.39,717.11 3839.36,717.11 3855,732.75 v1(3855,1231)
  L08 - BOTTOM w4.5: v1(3855,1231) 3887.03,1263.03 4389,1263.03 4416.28,1235.75 4490.84,1235.75 4506.71,1251.62 4581.26,1251.62 4598.73,1234.16 J11.13@4737.2,1234.16
PR1_PRU0_GPIO9: R121.2 U2.A13 U26.7 | length 2308.5
  L01 - TOP w4.3: v1(2337,597) 2312.15,621.85 2312.15,731.04 2330.33,749.21 2333.33,749.21 2333.98,749.21 2340,755.24 2340,756.02 2353.49,769.51 2353.49,776.34 2353.49,819.29 2355.6,821.41 2355.6,822.77 2358.77,825.94 U2.A13@2358.77,828.5
  L01 - TOP w4.5: U26.7@4283.87,545.76 4284.44,545.19 4284.44,501.56 v1(4285,501)
  L03 - SIG w4.5: v1(2337,597) 2463.76,597 2478.51,611.75 4108.25,611.75 4219,501 v1(4285,501)
PR1_PRU0_GPIO10: J11.15 U2.A19 | length 3103.1
  L01 - TOP w4.5: v1(2191,795) 2191,795.55 2205.23,809.78 U2.A19@2205.23,828.5
  L03 - SIG w4.5: v1(2191,795) 2191,703 2212,682 2364.29,682 2381.54,699.25 4213.4,699.25 4472,957.85 v1(4472,1253)
  L08 - BOTTOM w4.5: v1(4472,1253) 4481.27,1262.27 4585.46,1262.27 4587.95,1259.79 4692.13,1259.79 4694.77,1257.15 4694.77,1257.08 4698.01,1253.84 J11.15@4737.2,1253.84
PR1_PRU0_GPIO11: J11.16 U2.C2 | length 3100.7
  L01 - TOP w3.5: U2.C2@2640.27,879.69 2653.28,866.67 2687.6,866.67 2691.92,862.35 2729.83,862.35 2740.5,862.35 2749.15,871 v1(2752,871)
  L01 - TOP w4.3: v1(3791,1251) 4267.13,1251 4289.66,1273.53 4755.33,1273.53 4775.48,1253.37 v1(5073,1253.37)
  L06 - SIG w4.5: v1(2752,871) 2752,843.8 2821.3,774.5 3785.36,774.5 3791,780.14 v1(3791,1251)
  L08 - BOTTOM w4.3: J11.16@4962.8,1253.84 4963.03,1253.61 5072.76,1253.61 v1(5073,1253.37)
PR1_PRU0_GPIO12: J11.17 U2.D2 | length 2713.9
  L06 - SIG w4.5: v1(2640.27,905.28) 2666.62,878.92 2666.62,816.12 2729.5,753.25 3834.36,753.25 3837,755.89 v1(3837,1271)
  L08 - BOTTOM w4.5: v1(3837,1271) 3839.53,1273.53 J11.17@4737.2,1273.53
PR1_PRU0_GPIO13: J11.18 U2.D1 | length 3020
  L01 - TOP w4.5: U2.D1@2665.86,905.28 2678.13,893 2715.75,893 2724.16,901.42 2729.83,901.42 2730.42,901.42 v1(2733,904) ; v1(3745,1276) 3817.6,1276 3829.85,1288.25 3861.46,1288.25 3863.26,1286.45 4835.57,1286.45 4842.85,1293.73 4857.15,1293.73 4877.14,1273.74 v1(5043,1273.74)
  L06 - SIG w4.5: v1(2733,904) 2734,905 2755.4,905 2798.94,861.45 2798.94,841.41 2844.35,796 3742.36,796 3745,798.64 v1(3745,1276)
  L08 - BOTTOM w4.5: J11.18@4962.8,1273.53 4962.9,1273.63 5042.89,1273.63 v1(5043,1273.74)
PR1_PRU0_GPIO14: J11.19 U2.E2 | length 2645.9
  L01 - TOP w3.5: U2.E2@2640.27,930.87 2653.28,917.85 2675.73,917.85 2680.23,913.35 2717.35,913.35 2726,922 2729.83,922 2751,922 2771,902 v1(2811,902)
  L06 - SIG w4.5: v1(2811,902) 2811,886 2842.75,854.25 2864.15,854.25 2874.25,844.15 2874.25,842.75 2897.58,819.42 3701.36,819.42 3705,823.05 v1(3705,1299)
  L08 - BOTTOM w4.5: v1(3705,1299) 3708.14,1299 3714.39,1305.25 3858.15,1305.25 3870.65,1292.75 4492.58,1292.75 4493.04,1293.21 J11.19@4737.2,1293.21
PR1_PRU0_GPIO15: J11.20 U2.C1 | length 3175.1
  L01 - TOP w3.5: U2.C1@2665.86,879.69 2666.2,879.34 2725.66,879.34 v1(2726,879)
  L01 - TOP w4.3: v1(3810,1329) 3834,1329 3867.15,1295.85 4808.85,1295.85 4817.13,1304.13 4861.45,1304.13 4872.84,1292.74 v1(5073,1292.74)
  L06 - SIG w4.5: v1(2726,879) 2726,840 2729.83,836.17 2802,764 3808.36,764 3811,766.64 3811,1328 v1(3810,1329)
  L08 - BOTTOM w4.3: J11.20@4962.8,1293.21 4963.03,1292.98 5072.76,1292.98 v1(5073,1292.74)
PR1_PRU0_GPIO16: J11.21 U2.B2 | length 2551.7
  L01 - TOP w3.5: U2.B2@2640.27,854.09 2653.28,841.08 2697.92,841.08 v1(2725,814)
  L03 - SIG w4.5: v1(2725,814) 2838.6,814 2843.6,819 4211.06,819 4303.75,911.69 4303.75,1295 4307.42,1298.67 4307.42,1310.42 v1(4310,1313)
  L08 - BOTTOM w4.3: v1(4310,1313) 4310.05,1312.95 J11.21@4737.2,1312.9 J11.21@4737.2,1312.9
PR1_PRU0_GPIO17: J11.22 R217.1 U2.B9 U21.6 | length 3893.5
  L01 - TOP w3.5: v1(2384,513) 2381.23,515.77 2381.23,526.02 2378.25,529 2378.25,629.56 2387.75,639.06 2387.75,688.57 2387.25,689.07 2387.25,738.57 2396.36,747.69 2399.45,747.69 2404,752.24 R217.1@2404,753.02 ; R217.1@2405.13,756.45 2448,799.31 2448,823.82 2448.56,824.38 2448.56,841.52 U2.B9@2461.13,854.09
  L01 - TOP w4.3: v1(4088,1327) 4091.71,1327 4094.86,1330.15 4662.57,1330.15 4678.29,1314.43 5041.68,1314.43 v1(5043,1313.11)
  L06 - SIG w4.5: v1(2384,513) 2387.65,513 2392.9,507.75 2397.85,507.75 2409.85,495.75 2425.35,495.75 2443.17,513.57 2594.88,513.57 2609.07,499.38 2760.77,499.38 2769.15,507.75 2971.15,507.75 2987.65,524.25 3292.15,524.25 3294.65,521.75 3368.35,521.75 3368.85,522.25 3603.75,522.25 3616.25,509.75 3851.15,509.75 3868.4,527 3904.4,527 4089,711.6 4089,1326 v1(4088,1327)
  L08 - BOTTOM w4.3: v1(2384,513) 2393.13,503.87 U21.6@2393.13,484.65 ; J11.22@4962.8,1312.9 4962.9,1313 5042.89,1313 v1(5043,1313.11)
PR1_PRU0_GPIO18: J11.23 R13.1 U2.A9 U21.7 | length 3406.9
  L01 - TOP w3.5: v1(2417,513) 2475.75,571.75 2475.75,680.25 2445.45,710.55 2445.45,739.46 2440.1,744.81 2438.42,744.81 2431.59,751.65 v1(2431.59,754.4) 2452.6,775.41 ; 2452.6,774.64 2452.6,775.41 ; U2.A9@2461.13,828.5 2461.13,825.72 2457.96,822.55 2457.96,795.98 2452.6,790.62 2452.6,775.41
  L06 - SIG w4.5: v1(2431.59,754.4) 2492.98,754.4 2577.38,670 3906,670 3935,699 3935,1330 v1(3937,1332)
  L08 - BOTTOM w4.3: U21.7@2408.87,484.65 2408.87,504.15 2417,512.28 v1(2417,513)
  L08 - BOTTOM w4.5: v1(3937,1332) 3959.25,1309.75 4273.35,1309.75 4296.19,1332.58 J11.23@4737.2,1332.58
PR1_PRU0_GPIO19: J11.24 U2.B16 | length 3766.2
  L01 - TOP w4.5: U2.B16@2282,854.09 v1(2308,880) ; v1(3977,1335) 3980.65,1335 3989.9,1344.25 4663.18,1344.25 4675.32,1332.11 v1(5073,1332.11)
  L06 - SIG w4.5: v1(2308,880) 2308,878.76 2290.44,861.2 2290.44,821.4 2308,803.84 2308,776.34 2308,763.54 2381.54,690 2504,690 2561.35,632.65 3901.86,632.65 3979,709.79 3979,1333 v1(3977,1335)
  L08 - BOTTOM w4.5: J11.24@4962.8,1332.58 4963.03,1332.35 5072.76,1332.35 v1(5073,1332.11)
PR1_PRU0_GPIO20: J11.25 U2.C14 | length 3288.1
  L06 - SIG w4.5: v1(2333.18,879.69) 2357.43,879.69 2375.92,861.2 2375.92,830.95 2363.85,818.88 2363.85,776.34 2363.85,730.94 2393.79,701 2517,701 2560,658 3910,658 3957,705 v1(3957,1375)
  L08 - BOTTOM w4.3: v1(3957,1375) 3978.37,1353.63 4735.84,1353.63 J11.25@4737.2,1352.27
PR1_PRU1_GPIO0: J11.29 U2.W16 | length 2944.9
  L01 - TOP w3.5: U2.W16@2282,1289.13 2295.01,1302.15 2295.01,1319.93 2302.38,1327.3 2319.3,1327.3 v1(2341,1349)
  L03 - SIG w4.5: v1(2341,1349) 2372.7,1349 2468,1444.3 2468,1635.86 2470.64,1638.5 2644.41,1638.5 2655.91,1627 3031,1627 3075,1583 3836.51,1583 3839.15,1580.36 3839.15,1406.85 v1(3854,1392)
  L08 - BOTTOM w4.5: v1(3854,1392) 3854.25,1392.25 4237.02,1392.25 4259.02,1414.25 4297.35,1414.25 4319.97,1391.64 J11.29@4737.2,1391.64
PR1_PRU1_GPIO1: J11.30 U2.Y16 | length 3327
  L01 - TOP w3.5: U2.Y16@2282,1314.72 2283.97,1316.69 2283.97,1322.18 2298.49,1336.7 2311.79,1350 v1(2315,1350)
  L01 - TOP w4.3: v1(3937,1423) 3956.75,1423 3961.9,1428.15 4004.05,1428.15 4017.15,1415.05 4228.62,1415.05 4256.57,1443 4317.25,1443 4365.85,1394.4 4854.7,1394.4 4857.25,1391.85 v1(5043,1391.85)
  L03 - SIG w4.5: v1(2315,1350) 2315,1368.15 2365.68,1418.83 2365.68,1476.83 2457.13,1568.28 2457.13,1642.13 2489,1674 3009,1674 3083,1600 3933.36,1600 3936,1597.36 3936,1424 v1(3937,1423)
  L08 - BOTTOM w4.3: J11.30@4962.8,1391.64 4962.9,1391.74 5042.89,1391.74 v1(5043,1391.85)
PR1_PRU1_GPIO2: J11.31 U2.W17 | length 3011.8
  L01 - TOP w3.5: U2.W17@2256.41,1289.13 2269.42,1302.15 2269.42,1330.98 2275.45,1337 2275.45,1341.7 2283,1349.25 v1(2283,1351)
  L03 - SIG w4.5: v1(2283,1351) 2317.98,1385.98 2317.98,1508.98 2391.8,1582.8 2391.8,1614.06 2473.94,1696.19 3632.56,1696.19 3715.76,1613 3965,1613 3969,1609 v1(3969,1411)
  L08 - BOTTOM w4.5: v1(3969,1411) 4130.3,1411 4144.05,1424.75 4352.48,1424.75 4354.4,1422.83 4562.83,1422.83 4570.11,1430.11 4630.92,1430.11 4649.71,1411.32 J11.31@4737.2,1411.32
PR1_PRU1_GPIO3: U2.A12 U27.2 | length 2233.2
  L01 - TOP w4.3: v1(2381,795.73) 2383.62,798.35 2383.62,808.08 2384.36,808.82 U2.A12@2384.36,828.5 ; v1(4392,602) 4392.56,601.44 4422.94,601.44 U27.2@4423.5,600.87
  L03 - SIG w4.5: v1(2416,671) 2418.58,668.42 2431.71,668.42 2432.13,668 2441.6,668 2451.85,678.25 2466.15,678.25 2476.4,668 4268.85,668 4334.85,602 v1(4392,602)
  L08 - BOTTOM w4.5: v1(2381,795.73) 2381,793.26 2374.09,786.34 2374.09,776.44 2374.19,776.34 2374.19,697.36 2400.54,671 v1(2416,671)
PR1_PRU1_GPIO4: J11.33 U2.D11 | length 3226.6
  L06 - SIG w4.5: v1(2409.95,905.28) 2453.92,861.31 2455.77,861.31 2499.74,817.35 2524.91,817.35 2549.31,792.94 2549.31,748.1 2604.41,693 3892.51,693 3896,696.49 v1(3896,1428)
  L08 - BOTTOM w4.5: v1(3896,1428) 3939.75,1471.75 4002.15,1471.75 4015.65,1485.25 4203.15,1485.25 4203.4,1485 4298.4,1485 4339.4,1444 4391.18,1444 4401.85,1433.33 4489.03,1433.33 4496.31,1440.61 4635.27,1440.61 4644.87,1431.01 J11.33@4737.2,1431.01
PR1_PRU1_GPIO5: J11.34 U2.E1 | length 3204.7
  L01 - TOP w4.3: U2.E1@2665.86,930.87 2666.72,930 v1(2693,930) ; v1(3725,1428) 3742.15,1445.15 4001.62,1445.15 4021.42,1425.35 4224.35,1425.35 4259.15,1460.15 4323.1,1460.15 4373.25,1410 4565.89,1410 4585.9,1430.01 4600.1,1430.01 4607.96,1422.15 5033.78,1422.15 5042.84,1431.22 v1(5043,1431.22)
  L06 - SIG w4.5: v1(2693,930) 2695.58,927.42 2708.24,927.42 2711.07,924.58 2718.54,924.58 2724.83,930.87 2748.13,930.87 2839.75,839.25 2839.75,829.85 2862.6,807 3722.36,807 3725,809.64 v1(3725,1428)
  L08 - BOTTOM w4.3: J11.34@4962.8,1431.01 4962.9,1431.11 5042.89,1431.11 v1(5043,1431.22)
PR1_PRU1_GPIO6: J11.35 U2.A11 | length 2995.5
  L01 - TOP w4.5: v1(2401,781) 2401,781.43 2409.95,790.39 U2.A11@2409.95,828.5
  L03 - SIG w4.5: v1(2401,781) 2419.07,781 2422.76,784.69 2454.29,784.69 2462.64,776.34 2470.35,768.62 2586.22,768.62 2609.84,745 2847.06,745 2866.56,764.5 4230.8,764.5 4409,942.7 v1(4409,1450.58)
  L08 - BOTTOM w4.5: v1(4409,1450.58) 4491.43,1450.58 4491.96,1451.11 4639.62,1451.11 4640.03,1450.69 J11.35@4737.2,1450.69
PR1_PRU1_GPIO7: J11.36 U2.D15 | length 4298.5
  L01 - TOP w4.3: v1(4052,1445) 4055.71,1445 4060.71,1440 4224,1440 4254.45,1470.45 4331.94,1470.45 4377.39,1425 4566.32,1425 4581.63,1440.31 4824.06,1440.31 4843.9,1460.15 4858.1,1460.15 4868.03,1450.22 v1(5073,1450.22)
  L06 - SIG w4.5: v1(2307.59,905.28) 2280.71,905.28 2263.54,922.45 2217.97,922.45 2168.15,872.63 2168.15,842.9 2147,821.75 2147,716 2318,545 3015.6,545 3029.85,559.25 3134.15,559.25 3137.15,556.25 3646.15,556.25 3656.4,546 3874.61,546 4051,722.39 4051,1444 v1(4052,1445)
  L08 - BOTTOM w4.3: J11.36@4962.8,1450.69 4963.03,1450.46 5072.76,1450.46 v1(5073,1450.22)
PR1_PRU1_GPIO8: J11.37 U2.B11 | length 3011.7
  L03 - SIG w4.5: v1(2409.95,854.09) 2409.95,832.93 2419.74,823.15 2561.56,823.15 2629.21,755.5 2839.5,755.5 2859,775 4226.45,775 4381,929.55 v1(4381,1483.29)
  L08 - BOTTOM w4.5: v1(4381,1483.29) 4393.91,1470.38 J11.37@4737.2,1470.38
PR1_PRU1_GPIO9: J11.38 U2.Y17 | length 3347.6
  L01 - TOP w3.5: U2.Y17@2256.41,1314.72 2256.41,1331.26 2266.05,1340.9 2266.05,1364.13 2274,1372.08 v1(2274,1376)
  L01 - TOP w4.3: v1(4088,1468) 4105.7,1450.3 4219.73,1450.3 4250.18,1480.75 4336.2,1480.75 4350.82,1466.14 4388.1,1466.14 4389.69,1467.73 4416.1,1467.73 4433.22,1450.61 4819.79,1450.61 4839.63,1470.45 5042.86,1470.45 v1(5043,1470.59)
  L03 - SIG w4.5: v1(2274,1376) 2292.79,1394.79 2292.79,1510.33 2381.3,1598.85 2381.3,1618.41 2469.59,1706.69 3636.91,1706.69 3677.85,1665.75 4014.4,1665.75 4088,1592.15 v1(4088,1468)
  L08 - BOTTOM w4.3: J11.38@4962.8,1470.38 4962.9,1470.48 5042.89,1470.48 v1(5043,1470.59)
PR1_PRU1_GPIO10: J11.39 U2.C16 | length 3468.7
  L06 - SIG w4.5: v1(2282,879.69) 2282,878.2 2274.1,870.3 2274.1,821.15 2284.15,811.1 2284.15,776.34 2284.15,757.25 2393.9,647.5 2408.1,647.5 2433.46,622.15 3906.21,622.15 3996,711.94 3996,1488 v1(3995,1489)
  L08 - BOTTOM w4.5: v1(3995,1489) 4011.25,1505.25 4518.26,1505.25 4534.76,1488.75 4648.16,1488.75 4649.47,1490.06 J11.39@4737.2,1490.06
PR1_PRU1_GPIO11: J11.40 R16.2 U2.R2 | length 2991
  L01 - TOP w3.5: U2.R2@2640.27,1186.77 2652.84,1174.19 2682.87,1174.19 2689.32,1180.65 2711.54,1180.65 2729.05,1163.14 R16.2@2729.83,1163.14 ; v1(2728.6,1163) R16.2@2729.98,1163
  L01 - TOP w4.3: v1(4412,1488) 4412.8,1488.8 5072.2,1488.8 v1(5073,1489.59)
  L03 - SIG w4.5: v1(2728.6,1163) 2729.83,1161.76 2739.35,1152.25 2778.75,1152.25 2795.75,1135.25 2926.35,1135.25 2994.6,1067 4290.11,1067 4292.75,1069.64 4292.75,1320.15 4348.25,1375.65 4348.25,1474.93 4373.85,1500.54 4399.46,1500.54 v1(4412,1488)
  L08 - BOTTOM w4.3: J11.40@4962.8,1490.06 4963.03,1489.83 5072.76,1489.83 v1(5073,1489.59)
PR1_PRU1_GPIO12: J11.41 R120.2 U2.R1 | length 2521.4
  L01 - TOP w4.5: U2.R1@2665.86,1186.77 2681.44,1186.77 2685.67,1191 v1(2728.6,1191) R120.2@2729.98,1191
  L03 - SIG w4.5: v1(2728.6,1191) 2731.18,1188.42 2744.23,1188.42 2767.65,1165 2895.95,1165 2906.2,1154.75 2944.25,1154.75 3021,1078 3040.6,1078 3040.85,1077.75 4227.11,1077.75 4230,1080.64 4230,1136.4 4271.21,1177.6 4271.21,1313.45 4333,1375.24 v1(4333,1531)
  L08 - BOTTOM w4.5: v1(4333,1531) 4507.35,1531 4528.61,1509.75 J11.41@4737.2,1509.75
PR1_PRU1_GPIO13: J11.42 U2.B17 | length 4138.5
  L01 - TOP w4.5: v1(2256,879) 2256.2,878.8 2256.2,854.3 U2.B17@2256.41,854.09 ; v1(4015,1524) 4029.04,1509.96 v1(5043,1509.96)
  L06 - SIG w4.5: v1(2256,879) 2233.67,879 2168.9,814.23 2168.9,776.44 2169,776.34 2169,723.7 2317.85,574.85 2401.3,574.85 2425.7,599.25 2557.75,599.25 2568,589 3217.25,589 3229,577.25 3654.84,577.25 3657.91,574.19 3873.1,574.19 4015,716.09 v1(4015,1524)
  L08 - BOTTOM w4.5: J11.42@4962.8,1509.75 4962.9,1509.85 5042.89,1509.85 v1(5043,1509.96)
PR1_PRU1_GPIO14: U2.B18 U28.2 | length 2142.8
  L01 - TOP w3.5: v1(2212,582) 2212,776.34 2212,802.55 2217.81,808.35 2217.81,841.08 U2.B18@2230.82,854.09 ; v1(3970,468) 3971.06,466.94 4000.44,466.94 U28.2@4001.5,465.87
  L03 - SIG w4.5: v1(2212,582) 2212.27,582 2223.27,571 2237.51,571 2246.66,580.15 2329.6,580.15 2329.9,579.85 2344.1,579.85 2344.4,580.15 2461.75,580.15 2482.6,601 3027.06,601 3027.31,601.25 3275.82,601.25 3276.07,601 3737.5,601 3870.5,468 v1(3970,468)
PR1_PRU1_GPIO15: U2.C9 U27.5 | length 2262.8
  L01 - TOP w4.3: v1(4409,534) 4420.76,545.76 U27.5@4431.38,545.76
  L03 - SIG w4.5: v1(2459,661) 2460.94,661 2468.94,653 4268.13,653 4268.68,652.45 4269.55,652.45 4388,534 v1(4409,534)
  L08 - BOTTOM w4.3: v1(2459,661) 2461.13,663.13 2461.13,709.31 2444.95,725.49 2444.95,743.51 2452.59,751.15 2452.59,776.34 2452.59,869.72 2461.13,878.26 v1(2461.13,879.69)
PR1_PRU1_GPIO16: U2.D10 U27.7 | length 2412.7
  L01 - TOP w4.3: U27.7@4462.87,545.76 4462.94,545.69 4462.94,516.06 v1(4463,516)
  L03 - SIG w4.5: v1(2432.44,650) 2439.39,643.05 4264.1,643.05 4391.15,516 v1(4463,516)
  L08 - BOTTOM w4.3: v1(2432.44,650) 2432.18,650.25 2432.18,662.93 2433.15,663.9 2433.15,728.59 2409.95,751.79 2409.95,765.84 2418.05,773.94 2418.05,776.34 2418.05,788.06 2409.95,796.16 2409.95,796.35 2402.89,803.41 2402.89,837.04 2392.9,847.03 2392.9,862.64 v1(2435.54,905.28)
PR1_PRU1_GPIO17: R238.2 U28.5 | length 2020.2
  L01 - TOP w4.3: R238.2@2262.72,733.61 2262.72,732.83 2256.25,726.36 2256.25,572.37 2264,564.62 v1(2264,563)
  L01 - TOP w4.5: v1(3988,391) 3990.58,393.58 4000.08,393.58 4009.38,402.88 U28.5@4009.38,410.76
  L03 - SIG w4.5: v1(2264,563) 3018.76,563 3036.01,580.25 3713,580.25 3902.25,391 v1(3988,391)
PR1_PRU1_GPIO18: U2.A16 U28.7 | length 2203.4
  L01 - TOP w4.3: U2.A16@2282,828.5 2282,813.11 2284.05,811.06 2284.05,776.34 2284.05,730.03 2266.55,712.53 2266.55,599.45 2284,582 v1(2284,545) ; U28.7@4040.87,410.76 4040.87,389.72 4050,380.6 v1(4050,377)
  L03 - SIG w4.5: v1(2284,545) 3015.6,545 3040.35,569.75 3690,569.75 3896,363.75 4036.75,363.75 v1(4050,377)
PR1_PRU1_GPIO19: U2.C7 U28.10 | length 2047.6
  L01 - TOP w3.5: v1(2502,582) 2504.63,584.63 2504.63,765 2515.97,776.34 2523.89,776.34 2537.65,790.1 2537.65,803.9 2525.33,816.22 2525.33,866.67 U2.C7@2512.31,879.69
  L01 - TOP w4.5: U28.10@4064.5,450.13 4087.22,450.13 4095.35,442 v1(4099,442)
  L03 - SIG w4.5: v1(2502,582) 3022.91,582 3031.66,590.75 3721.25,590.75 3894,418 4005,418 4029,442 v1(4099,442)
SEL_HPI_FSI: R118.2 U7.9 U26.15 U27.15 | length 4214.2
  L01 - TOP w4.3: v1(1518.45,626.91) 1518.45,623.2 1524.35,617.29 U7.9@1524.35,595.41 ; U27.15@4447.13,640.24 4447.13,667.01 4445.35,668.78 4445.35,696.01 4463.35,714 R118.2@4465.31,714
  L01 - TOP w4.5: U26.15@4268.13,640.24 4268.13,684.13 4302.24,718.25 4461.06,718.25 R118.2@4465.31,714
  L03 - SIG w4.5: v1(1518.45,626.91) 1695.34,626.91 1767.47,554.78 2054.51,554.78 2364.18,245.1 2364.18,190.54 2499.97,54.75 4186.82,54.75 4240.35,108.29 4240.35,393.61 4302.15,455.4 4426.66,455.4 4480.15,508.9 4480.15,570.1 4373,677.25 v1(4373,718)
SEL_HPI_SPI: R119.2 U7.10 U28.15 | length 2845.4
  L01 - TOP w4.5: v1(1495,591) 1498.65,591 1507.6,582.05 1510.94,582.05 1517.27,575.72 U7.10@1524.35,575.72 ; v1(3744,482) 3925.4,482 3977.87,534.48 3977.87,538.27 4011.6,572 R119.2@4042.35,572 ; U28.15@4025.13,505.24 4024.25,506.12 4024.25,553.91 R119.2@4042.35,572 ; R119.2@4044.31,572 R119.2@4042.35,572
  L06 - SIG w4.5: v1(1495,591) 1541.6,591 1553.28,602.68 1719.43,602.68 1824.85,497.25 2300.35,497.25 2332.35,465.25 2509.75,465.25 2580,395 2783,395 2805.25,372.75 2908.64,372.75 2922.64,386.75 3328.15,386.75 3423.4,482 v1@3745,482
SEL_MMC: J18.2 R180.2 U49.15 U52.15 | length 559.3
  L01 - TOP w6: v1(2562,448) 2577.13,432.87 U52.15@2577.13,410.24 ; v1(2774,447) 2774,443.75 2781.13,436.63 U49.15@2781.13,411.24
  L08 - BOTTOM w6: v1(2562,448) R180.2@2594.38,448 ; R180.2@2597.31,449 2617,429.31 2617,406.51 2620.51,403 2642.46,403 2679.46,440 2744.46,440 2751.21,446.75 2773.75,446.75 v1(2774,447) 2848,447 J18.2@2949,346
SHIELD_USB: C138.2 J14.1 J14.2 J14.3 J14.4 J14.5 J14.6 J14.7 J14.8 R144.1 | length 1436.8
  L01 - TOP w20: v1(2303,3547.74) 2331.74,3519 J14.8@2378,3519 ; J14.5@2378,3396.95 2378,3400.57 2450,3472.57 2450,3554.04 v1(2452.76,3556.8)
  L03 - SIG w20: J14.4@2209.89,3311.13 2208,3309.24 2208,3266 2258,3216 2299,3216 2299.26,3216.26 J14.2@2299.26,3265.85 ; J14.1@2456.74,3265.85 2457.81,3264.78 2457.81,3255.55 2490.36,3223 2517,3223 2546.11,3252.11 J14.3@2546.11,3311.13
  L08 - BOTTOM w20: J14.4@2209.89,3311.13 J14.7@2209.89,3497.35 2209.89,3503.92 2232.22,3526.24 2281.5,3526.24 v1(2303,3547.74) 2438.19,3547.74 R144.1@2450,3559.55 v1(2452.76,3556.8) 2471.5,3538.06 2511.97,3538.06 2546.11,3503.92 J14.6@2546.11,3497.35 J14.3@2546.11,3311.13
SHIELD_USB2: C129.1 J13.6 J13.7 J13.8 J13.9 J13.10 J13.11 R139.2
  other v1: 3207,3587 3246.32,3587.8 3283,3588
SHIELD_XDS: C141.1 J15.6 J15.7 J15.8 J15.9 J15.10 J15.11 R153.2
  other v1: 4214,3579 4247,3578.74 4285.69,3578.74
SOP0_SW: R127.1 SW6.8 U32.6 | length 406.4
  L01 - TOP w5: U32.6@1733.99,179.41 1733.99,95.01 1756,73 1952,73 v1(1966,87) 2006.79,87 SW6.8@2007.36,87.57
  L08 - BOTTOM w8: v1(1966,87) 1998.09,87 R127.1@1999.09,86
SOP1_SW: R126.1 SW6.7 U32.7 | length 324.4
  L01 - TOP w5: U32.7@1749.74,179.41 1749.74,153.26 1766,137 v1(1966,137) 2006.79,137 SW6.7@2007.36,137.57
  L08 - BOTTOM w8: v1(1966,137) 1997.76,137 R126.1@1999.09,135.67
